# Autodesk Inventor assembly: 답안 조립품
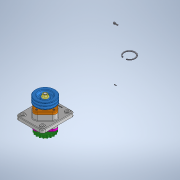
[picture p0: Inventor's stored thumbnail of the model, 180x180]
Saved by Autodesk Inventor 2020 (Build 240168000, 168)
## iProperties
Created: 2021-07
Part Number: 답안 조립품
Document SubType Name: Assembly
Designer: Owner
Author: Owner
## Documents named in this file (17)
- C:\Users\Owner\Desktop\710707V1007\답안 조립품.iam
- C:\Users\Owner\Desktop\710707V1007\본체.ipt
- C:\Users\Owner\Desktop\710707V1007\M16 너트.ipt
- C:\Users\Owner\Desktop\710707V1007\V-벨트풀리.ipt
- C:\Users\Owner\Desktop\710707V1007\멈춤나사 M4.ipt
- C:\Users\Owner\Desktop\710707V1007\멈춤링 62x65x2.ipt
- C:\Users\Owner\Desktop\710707V1007\베어링 6206.ipt
- C:\Users\Owner\Desktop\710707V1007\볼트 M6.ipt
- C:\Users\Owner\Desktop\710707V1007\부시.ipt
- C:\Users\Owner\Desktop\710707V1007\오일실 30x42x8.ipt
- C:\Users\Owner\Desktop\710707V1007\오일실 30x45x8.ipt
- C:\Users\Owner\Desktop\710707V1007\체인 스프로킷.ipt
- C:\Users\Owner\Desktop\710707V1007\축.ipt
- C:\Users\Owner\Desktop\710707V1007\커버A.ipt
- C:\Users\Owner\Desktop\710707V1007\커버B.ipt
- C:\Users\Owner\Desktop\710707V1007\키 6x6x18.ipt
- C:\Users\Owner\Desktop\710707V1007\키 6x6x20.ipt
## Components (3 placed, 2 different names)
1. M16 너트:1
2. V-벨트풀리:1
3. M16 너트:2
